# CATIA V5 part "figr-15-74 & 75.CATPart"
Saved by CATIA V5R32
Part number: Part1
Bounding box of the stored display mesh (mm): x -68.209 to 30, y -98.209 to 60, z 0 to 98
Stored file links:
  D:\PROJECTS\Project 2022\CATIA V5 6R 2022\Resources\Part Files\c15_catia_v5_6r2022_prt\figr-15-74 & 75.CATPart
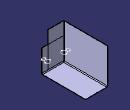
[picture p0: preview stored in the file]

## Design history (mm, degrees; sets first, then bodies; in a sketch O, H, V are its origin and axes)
SheetMetalParameters1: Thickness 1, BendRadius 2, KFactor 0.400515 {= log(min(100,max(20*SheetMetalParameters1.BendRadius,SheetMetalParameters1.Thickness)/SheetMetalParameters1.Thickness))/log(100)/2}, ReliefRadialLength 1, ReliefAxialLength 2, MinimumBendRadius 0
Body1 (main body)
  Sketch1 on xy-plane, origin (0, 0, 0), H (1, 0, 0), V (0, 1, 0)
    line L1 (-30, 60) -> (30, 60)
    line L2 (30, 60) -> (30, -60)
    line L3 (30, -60) -> (-30, -60)
    line L4 (-30, -60) -> (-30, 60)
    length L2 = 120
    length L1 = 60
    distance V L2 = 30
    distance H L1 = 60
    horizontal: L1 H, L3 H
    vertical: L2 V, L4 V
  Wall1: Thickness 1, Profile Sketch1
  d_NewWallOnEdge1: NewWallOnEdge_Edge edge [face of Wall1 | face of Wall1], NewWallOnEdge_Length 98, NewWallOnEdge_HeightLimitOffset 0, NewWallOnEdge_WidthOffset1 0, NewWallOnEdge_WidthOffset2 0, NewWallOnEdge_Angle 90, NewWallOnEdge_BendRadiusValue 2 {= SheetMetalParameters1.BendRadius}, NewWallOnEdge_BendTable SheetMetalParameters1, KFacteur 0.400515 {= log(min(100,max(20*d_NewWallOnEdge1.Radius,SheetMetalParameters1.Thickness)/SheetMetalParameters1.Thickness))/log(100)/2}
  d_NewWallOnEdge2: NewWallOnEdge_Edge edge [face of Wall1 | face of Wall1], NewWallOnEdge_Length 63, NewWallOnEdge_HeightLimitOffset 0, NewWallOnEdge_WidthOffset1 0, NewWallOnEdge_WidthOffset2 0, NewWallOnEdge_Angle 90, NewWallOnEdge_BendRadiusValue 2 {= SheetMetalParameters1.BendRadius}, NewWallOnEdge_BendTable SheetMetalParameters1, KFacteur 0.400515 {= log(min(100,max(20*d_NewWallOnEdge2.Radius,SheetMetalParameters1.Thickness)/SheetMetalParameters1.Thickness))/log(100)/2}
  d_NewWallOnEdge3: NewWallOnEdge_Edge edge [face of d_NewWallOnEdge1 | face of d_NewWallOnEdge1], NewWallOnEdge_Length 44, NewWallOnEdge_HeightLimitOffset 0, NewWallOnEdge_WidthOffset1 0, NewWallOnEdge_WidthOffset2 0, NewWallOnEdge_Angle 90, NewWallOnEdge_BendRadiusValue 2 {= SheetMetalParameters1.BendRadius}, NewWallOnEdge_BendTable SheetMetalParameters1, KFacteur 0.400515 {= log(min(100,max(20*d_NewWallOnEdge3.Radius,SheetMetalParameters1.Thickness)/SheetMetalParameters1.Thickness))/log(100)/2}
  Sketch2 on face of d_NewWallOnEdge3, origin (0, -60, 0), H (-1, 0, 0), V (0, 0, 1)
    circle A1 centre (8.1625, 34.9685) radius 4.4696
    circle A2 centre (8.1625, 23.754) radius 6.7449
    tangency: A2 A1
  SHMMapping1: CATSHMMappingContext d_NewWallOnEdge3, CATSHMMappingObject Sketch2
